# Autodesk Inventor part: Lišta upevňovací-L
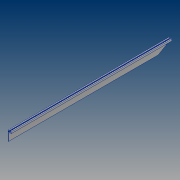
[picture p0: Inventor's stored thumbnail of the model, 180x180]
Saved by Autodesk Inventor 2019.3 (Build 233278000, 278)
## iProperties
Created: 2019-02
Part Number: Lišta upevňovací-L
Material: Hliník 6061
Document SubType Name: Modeling
Designer: B-hon
Density: 2.7 g/cm^3
Appearance: Hliník – plochý
Author: B-hon
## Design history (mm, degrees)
sketch "Náčrt1"
  geometry: L1 (0, 0)-(5, 0); L2 (30, 78)-(30, 95); L3 (0, 95)-(0, 0); L4 (5, 0)-(5, 78); L5 (5, 78)-(30, 78); L6 (5, 90.5)-(5, 82.5); L7 (25, 82.5)-(25, 90.5); L8 (9.55, 82.5)-(9.55, 85.5); L9 (9.55, 85.5)-(7.55, 85.5); L10 (7.55, 85.5)-(7.55, 82.5); L11 (22.45, 82.5)-(22.45, 85.5); L12 (22.45, 85.5)-(20.45, 85.5); L13 (20.45, 85.5)-(20.45, 82.5); L14 (5, 82.5)-(7.55, 82.5); L15 (9.55, 82.5)-(20.45, 82.5); L16 (22.45, 82.5)-(25, 82.5); L17 (9.55, 95)-(9.55, 90.5); L18 (20.45, 95)-(20.45, 90.5); L19 (30, 95)-(20.45, 95); L20 (9.55, 95)-(0, 95); L21 (25, 90.5)-(20.45, 90.5); L22 (9.55, 90.5)-(5, 90.5)
  constraints: 44 end point, 13 parallel, 6 perpendicular, 3 horizontal, 2 horizontal alignment, 1 point on line, 1 vertical
  dimensions: "d0" = 30 distance of L3.start L2.end; "d3" = 5 distance between parallel lines of L3 L6; "d4" = 5 distance between parallel lines of L2 L7; "d7" = 5 distance between parallel lines of L3 L4; "d8" = 14.9 distance between parallel lines of L11 L10; "d9" = 2 distance between parallel lines of L8 L10; "d10" = 2 distance of L11.end L12.end; "d14" = 2.55 distance between parallel lines of L10 L6; "d15" = 9.55 distance of L17.start L3.start; "d16" = 9.55 distance of L2.end L18.start (= d15); "d17" = 9.5 distance between parallel lines of L12 L19; "d18" = 12.5 distance between parallel lines of L19 L15; "d19" = 17 distance between parallel lines of L5 L19
extrude "Vysunutí1" new body sketch "Náčrt1" distance "d20" = 1600; taper "d21" = 0 deg
chamfer "Zkosení2" distance "d25" = 65; stored, may be unused: second distance "d26" = 2, angle "d27" = 60 deg
node "Těleso1"
other parameters: "d2" = 4.5, "d5" = 17, "d6" = 12.5, "d12" = 12.5, "d13" = 9.5
